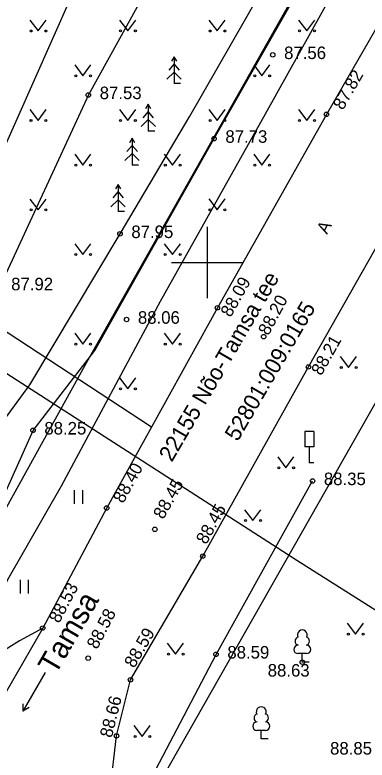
# Model space of a CAD drawing. Extents: x 648748 to 649126, y 6457789 to 6458252.
# Drawn here: x 648789.26 to 648808.93, y 6457972.19 to 6458013.84 of the extents above; entities that cross this region are included whole.
import ezdxf

# ---------------------------------------------------------------- set-up
doc = ezdxf.new("R2010")
doc.units = 0
for name, color, linetype in [('HALJASTUS', 7, 'Continuous'), ('KORGUS-EH2000', 7, 'Continuous'), ('LIIKLUS', 7, 'Continuous'), ('PIIR', 7, 'Continuous'), ('PUU', 7, 'Continuous'), ('SITRASS', 7, 'Continuous'), ('TEE', 7, 'Continuous'), ('VORK', 7, 'Continuous'), ('VTRASS', 7, 'Continuous')]:
    doc.layers.add(name, color=color, linetype=linetype)

msp = doc.modelspace()

# ---------------------------------------------------------------- linework, layer by layer
at = {"layer": 'HALJASTUS'}
for p, q in [((648790.094, 6458013.549), (648790.557, 6458012.942)), ((648790.557, 6458012.942), (648791.003, 6458013.549)), ((648795.092, 6458013.553), (648795.555, 6458012.946)), ((648795.555, 6458012.946), (648796.001, 6458013.553)), ((648800.094, 6458013.549), (648800.557, 6458012.942)), ((648800.557, 6458012.942), (648801.003, 6458013.549)), ((648805.092, 6458013.553), (648805.555, 6458012.946)), ((648805.555, 6458012.946), (648806.001, 6458013.553)), ((648792.594, 6458011.049), (648793.057, 6458010.442)), ((648793.057, 6458010.442), (648793.503, 6458011.049)), ((648802.594, 6458011.049), (648803.057, 6458010.442)), ((648803.057, 6458010.442), (648803.503, 6458011.049)), ((648790.092, 6458008.553), (648790.555, 6458007.946)), ((648790.555, 6458007.946), (648791.001, 6458008.553)), ((648795.092, 6458008.553), (648795.555, 6458007.946)), ((648795.555, 6458007.946), (648796.001, 6458008.553)), ((648800.094, 6458008.549), (648800.557, 6458007.942)), ((648800.557, 6458007.942), (648801.003, 6458008.549)), ((648805.094, 6458008.549), (648805.557, 6458007.942)), ((648805.557, 6458007.942), (648806.003, 6458008.549)), ((648792.594, 6458006.049), (648793.057, 6458005.442)), ((648793.057, 6458005.442), (648793.503, 6458006.049)), ((648797.594, 6458006.049), (648798.057, 6458005.442)), ((648798.057, 6458005.442), (648798.503, 6458006.049)), ((648802.592, 6458006.053), (648803.055, 6458005.446)), ((648803.055, 6458005.446), (648803.501, 6458006.053)), ((648790.094, 6458003.549), (648790.557, 6458002.942)), ((648790.557, 6458002.942), (648791.003, 6458003.549)), ((648800.092, 6458003.552), (648800.555, 6458002.946)), ((648800.555, 6458002.946), (648801.001, 6458003.552)), ((648792.594, 6458001.049), (648793.057, 6458000.442)), ((648793.057, 6458000.442), (648793.503, 6458001.049)), ((648797.592, 6458001.052), (648798.055, 6458000.446)), ((648798.055, 6458000.446), (648798.501, 6458001.052)), ((648784.11, 6457999.185), (648796.889, 6457990.818)), ((648792.594, 6457996.049), (648793.057, 6457995.442)), ((648793.057, 6457995.442), (648793.503, 6457996.049)), ((648797.594, 6457996.049), (648798.057, 6457995.442)), ((648798.057, 6457995.442), (648798.503, 6457996.049)), ((648807.425, 6457994.744), (648807.888, 6457994.137)), ((648807.888, 6457994.137), (648808.334, 6457994.744)), ((648795.092, 6457993.552), (648795.555, 6457992.946)), ((648795.555, 6457992.946), (648796.001, 6457993.552)), ((648803.934, 6457989.13), (648804.397, 6457988.523)), ((648804.397, 6457988.523), (648804.843, 6457989.13)), ((648792.568, 6457987.27), (648792.568, 6457986.509)), ((648793.023, 6457987.27), (648793.023, 6457986.509)), ((648802.078, 6457986.179), (648802.542, 6457985.573)), ((648802.542, 6457985.573), (648802.987, 6457986.179)), ((648789.548, 6457982.264), (648789.548, 6457981.503)), ((648790.003, 6457982.264), (648790.003, 6457981.503)), ((648807.819, 6457979.841), (648808.282, 6457979.234)), ((648808.282, 6457979.234), (648808.728, 6457979.841)), ((648797.764, 6457978.72), (648798.228, 6457978.114)), ((648798.228, 6457978.114), (648798.673, 6457978.72)), ((648795.903, 6457974.121), (648796.366, 6457973.514)), ((648796.366, 6457973.514), (648796.812, 6457974.121))]:
    msp.add_line(p, q, dxfattribs=at)
msp.add_lwpolyline([(648805.429, 6457958.346), (648802, 6457959.786), (648797.402, 6457964.175), (648796.042, 6457966.769), (648795.928, 6457969.389), (648800.489, 6457978.098), (648805.882, 6457987.791)], dxfattribs=at)
for centre in [(648790.156, 6458012.942), (648790.985, 6458012.942), (648795.154, 6458012.946), (648795.983, 6458012.946), (648800.156, 6458012.942), (648800.985, 6458012.942), (648805.154, 6458012.946), (648805.983, 6458012.946), (648792.656, 6458010.442), (648793.485, 6458010.442), (648802.656, 6458010.442), (648803.485, 6458010.442), (648790.154, 6458007.946), (648790.983, 6458007.946), (648795.154, 6458007.946), (648795.983, 6458007.946), (648800.156, 6458007.942), (648800.985, 6458007.942), (648805.156, 6458007.942), (648805.985, 6458007.942), (648792.656, 6458005.442), (648793.485, 6458005.442), (648797.656, 6458005.442), (648798.485, 6458005.442), (648802.654, 6458005.446), (648803.483, 6458005.446), (648790.156, 6458002.942), (648790.985, 6458002.942), (648800.154, 6458002.946), (648800.983, 6458002.946), (648792.656, 6458000.442), (648793.485, 6458000.442), (648797.654, 6458000.446), (648798.483, 6458000.446), (648792.656, 6457995.442), (648793.485, 6457995.442), (648797.656, 6457995.442), (648798.485, 6457995.442), (648807.487, 6457994.137), (648808.316, 6457994.137), (648795.154, 6457992.946), (648795.983, 6457992.946), (648803.996, 6457988.523), (648804.825, 6457988.523), (648802.141, 6457985.573), (648802.97, 6457985.573), (648807.881, 6457979.234), (648808.71, 6457979.234), (648797.827, 6457978.114), (648798.656, 6457978.114), (648795.965, 6457973.514), (648796.794, 6457973.514)]:
    msp.add_circle(centre, 0.055, dxfattribs=at)
at = {"layer": 'KORGUS-EH2000'}
for centre in [(648803.658, 6458011.607), (648793.359, 6458009.366), (648806.656, 6458008.281), (648800.38, 6458006.925), (648795.127, 6458001.6), (648800.566, 6457997.472), (648795.493, 6457996.812), (648803.15, 6457995.858), (648805.652, 6457994.165), (648790.268, 6457990.62), (648805.882, 6457987.791), (648794.382, 6457986.281), (648797.072, 6457985.085), (648799.747, 6457983.584), (648790.808, 6457979.567), (648793.349, 6457977.884), (648800.489, 6457978.098), (648805.307, 6457977.663), (648795.708, 6457976.678), (648794.926, 6457973.54)]:
    msp.add_circle(centre, 0.125, dxfattribs=at)
at = {"layer": 'LIIKLUS'}
for points in [[(648805.45, 6457990.547), (648805.45, 6457989.697)], [(648805.95, 6457990.547), (648805.45, 6457990.547)], [(648805.95, 6457990.547), (648805.95, 6457989.697)], [(648805.95, 6457989.697), (648805.45, 6457989.697)], [(648805.7, 6457989.697), (648805.7, 6457988.797)], [(648805.95, 6457988.797), (648805.7, 6457988.797)]]:
    msp.add_lwpolyline(points, dxfattribs=at)
at = {"layer": 'PIIR'}
for p, q in [((648868.92, 6458128.41), (648793.25, 6457994.41)), ((648796.52, 6457969.47), (648863.67, 6458087.81)), ((648793.25, 6457994.41), (648782.79, 6457975.49))]:
    msp.add_line(p, q, dxfattribs=at)
at = {"layer": 'PUU'}
for p, q in [((648798.146, 6458011.499), (648797.996, 6458011.249)), ((648798.296, 6458011.249), (648798.146, 6458011.499)), ((648798.146, 6458011.499), (648798.146, 6458009.999)), ((648798.146, 6458011.099), (648797.846, 6458010.749)), ((648798.446, 6458010.749), (648798.146, 6458011.099)), ((648798.146, 6458010.649), (648797.746, 6458010.249)), ((648798.546, 6458010.249), (648798.146, 6458010.649)), ((648798.506, 6458009.999), (648798.146, 6458009.999)), ((648796.702, 6458008.845), (648796.552, 6458008.595)), ((648796.852, 6458008.595), (648796.702, 6458008.845)), ((648796.702, 6458008.845), (648796.702, 6458007.345)), ((648796.702, 6458008.445), (648796.402, 6458008.095)), ((648797.002, 6458008.095), (648796.702, 6458008.445)), ((648796.702, 6458007.995), (648796.302, 6458007.595)), ((648797.102, 6458007.595), (648796.702, 6458007.995)), ((648797.062, 6458007.345), (648796.702, 6458007.345)), ((648795.798, 6458006.947), (648795.648, 6458006.697)), ((648795.948, 6458006.697), (648795.798, 6458006.947)), ((648795.798, 6458006.947), (648795.798, 6458005.447)), ((648795.798, 6458006.547), (648795.498, 6458006.197)), ((648796.098, 6458006.197), (648795.798, 6458006.547)), ((648795.798, 6458006.097), (648795.398, 6458005.697)), ((648796.198, 6458005.697), (648795.798, 6458006.097)), ((648796.158, 6458005.447), (648795.798, 6458005.447)), ((648795.02, 6458004.361), (648794.87, 6458004.111)), ((648795.17, 6458004.111), (648795.02, 6458004.361)), ((648795.02, 6458004.361), (648795.02, 6458002.861)), ((648795.02, 6458003.961), (648794.72, 6458003.611)), ((648795.32, 6458003.611), (648795.02, 6458003.961)), ((648795.02, 6458003.511), (648794.62, 6458003.111)), ((648795.42, 6458003.111), (648795.02, 6458003.511)), ((648795.38, 6458002.861), (648795.02, 6458002.861)), ((648805.547, 6457978.138), (648805.067, 6457978.138)), ((648805.307, 6457977.663), (648805.307, 6457978.138)), ((648805.687, 6457977.663), (648805.307, 6457977.663)), ((648803.255, 6457973.844), (648802.775, 6457973.844)), ((648803.015, 6457973.369), (648803.015, 6457973.844)), ((648803.395, 6457973.369), (648803.015, 6457973.369))]:
    msp.add_line(p, q, dxfattribs=at)
for centre, radius, start, end in [((648805.307, 6457979.183), 0.277, 332.58, 207.42), ((648805.137, 6457978.835), 0.233, 109.022, 253.142), ((648805.477, 6457978.835), 0.233, 286.851, 70.986), ((648805.07, 6457978.375), 0.238, 90.002, 269.395), ((648805.545, 6457978.375), 0.238, 270.605, 89.998), ((648803.015, 6457974.889), 0.277, 332.58, 207.42), ((648802.845, 6457974.542), 0.233, 109.022, 253.142), ((648803.185, 6457974.542), 0.233, 286.851, 70.986), ((648802.778, 6457974.082), 0.238, 90.002, 269.395), ((648803.253, 6457974.082), 0.238, 270.605, 89.998)]:
    msp.add_arc(centre, radius, start, end, dxfattribs=at)
at = {"layer": 'SITRASS'}
for points in [[(648838.183, 6458075.605), (648836.351, 6458076.524), (648834.032, 6458074.854), (648828.836, 6458070.077), (648823.373, 6458063.799), (648815.041, 6458050.907), (648808.674, 6458038.587), (648805.571, 6458032.708), (648798.852, 6458019.324), (648793.359, 6458009.366), (648788.414, 6457998.68), (648785.353, 6457991.074), (648783.686, 6457988.513), (648778.988, 6457980.101), (648777.337, 6457977.723), (648774.295, 6457973.649), (648772.508, 6457971.285), (648769.936, 6457967.433)], [(648840.698, 6458076.036), (648840.206, 6458074.518), (648835.992, 6458066.48), (648829.455, 6458054.737), (648823.386, 6458043.337), (648816.202, 6458031.074), (648810.097, 6458020.648), (648803.233, 6458008.294), (648797.369, 6457997.813), (648791.835, 6457987.5), (648788.847, 6457982.267), (648783.409, 6457971.182), (648777.403, 6457959.148), (648772.285, 6457949.688)], [(648771.558, 6457962.366), (648777.323, 6457971.169), (648780.294, 6457977.006), (648783.881, 6457983.462), (648786.386, 6457988.106), (648790.088, 6457993.164), (648795.127, 6458001.6), (648799.018, 6458008.179), (648807.603, 6458023.185), (648816.805, 6458039.666), (648823.715, 6458052.086), (648829.839, 6458063.342), (648833.461, 6458069.995), (648835.841, 6458074.502), (648836.926, 6458074.748), (648838.183, 6458075.605)], [(648772.534, 6457959.145), (648778.305, 6457968.987), (648782.296, 6457976.466), (648786.131, 6457983.091), (648788.533, 6457986.692), (648790.268, 6457990.62), (648793.726, 6457995.075), (648800.38, 6458006.925), (648808.978, 6458022.031), (648818.066, 6458038.429), (648824.931, 6458050.586), (648831.029, 6458061.413), (648834.793, 6458068.888), (648838.183, 6458075.605), (648839.481, 6458073.453), (648841.568, 6458071.264), (648846.872, 6458065.923), (648848.753, 6458063.394)]]:
    msp.add_lwpolyline(points, dxfattribs=at)
at = {"layer": 'TEE'}
for p in [(648790.948, 6457977.084), (648789.702, 6457975.33), (648790.06, 6457975.124)]:
    msp.add_line(p, (648789.702, 6457974.916), dxfattribs=at)
for points in [[(648844.3, 6458074.59), (648841.568, 6458069.96), (648835.932, 6458060.036), (648830.008, 6458049.677), (648824.317, 6458039.384), (648818.356, 6458028.958), (648812.613, 6458018.629), (648806.656, 6458008.281), (648800.566, 6457997.472), (648794.382, 6457986.281), (648790.808, 6457979.567), (648784.572, 6457968.758), (648779.694, 6457960.62), (648774.527, 6457951.036)], [(648795.708, 6457976.678), (648799.747, 6457983.584), (648805.652, 6457994.165), (648811.974, 6458005.315), (648817.667, 6458015.456), (648823.8, 6458025.997), (648829.771, 6458036.425), (648835.506, 6458046.826), (648841.055, 6458057.292), (648846.734, 6458067.377), (648849.159, 6458071.672)], [(648790.808, 6457979.567), (648789.507, 6457978.851), (648786.354, 6457976.876), (648782.643, 6457976.445), (648778.503, 6457977.377), (648774.153, 6457980.236)], [(648805.276, 6457956.318), (648804.322, 6457956.439), (648802.346, 6457956.554), (648796.623, 6457961.769), (648794.959, 6457965.9), (648794.568, 6457970.483), (648794.926, 6457973.54), (648795.708, 6457976.678)]]:
    msp.add_lwpolyline(points, dxfattribs=at)
at = {"layer": 'VORK'}
for p, q in [((648800, 6458002), (648800, 6457998)), ((648798, 6458000), (648802, 6458000))]:
    msp.add_line(p, q, dxfattribs=at)
at = {"layer": 'VTRASS'}
for p, q in [((648818.874, 6458074.609), (648784.329, 6457996.666)), ((648784.329, 6457996.666), (648805.004, 6457983.361)), ((648805.004, 6457983.361), (648828.053, 6457968.736))]:
    msp.add_line(p, q, dxfattribs=at)

# ---------------------------------------------------------------- texts
at = {"layer": 'KORGUS-EH2000'}
for s, p in [(' 87.56', (648804.031, 6458011.373)), (' 87.53', (648793.731, 6458009.133)), (' 87.73', (648800.752, 6458006.692)), (' 87.95', (648795.499, 6458001.367)), (' 87.92', (648788.786, 6457998.447)), (' 88.06', (648795.866, 6457996.579)), (' 88.25', (648790.64, 6457990.387)), (' 88.35', (648806.254, 6457987.557)), (' 88.59', (648800.862, 6457977.865)), ('88.63', (648803.376, 6457976.856)), ('88.85', (648806.859, 6457972.496))]:
    msp.add_text(s, height=0.7, dxfattribs=at).set_placement(p)
for s, rotation, p in [(' 87.82', 60.072, (648807.448, 6458008.254)), (' 88.09', 60.6012, (648801.176, 6457996.671)), (' 88.20', 61.836, (648803.291, 6457995.649)), (' 88.21', 60.4458, (648806.238, 6457993.41)), (' 88.40', 61.0775, (648795.175, 6457986.268)), (' 88.45', 60.1663, (648797.41, 6457985.379)), (' 88.45', 60.8351, (648799.814, 6457983.973)), (' 88.53', 61.9716, (648791.601, 6457979.567)), (' 88.58', 62.6594, (648793.727, 6457978.108)), (' 88.59', 59.6796, (648795.786, 6457977.064)), (' 88.66', 75.9994, (648794.602, 6457973.147))]:
    msp.add_text(s, height=0.7, rotation=rotation, dxfattribs=at).set_placement(p)
at = {"layer": 'PIIR'}
for s, p in [('22155 Nõo-Tamsa tee', (648798.02, 6457988.801)), ('52801:009:0165', (648801.698, 6457989.955))]:
    msp.add_text(s, height=0.9, rotation=59.7525, dxfattribs=at).set_placement(p)
at = {"layer": 'TEE'}
for s, height, rotation, p in [('A', 0.7, 62.2738, (648806.689, 6458001.544)), ('Tamsa', 1.2, 59.8074, (648791.518, 6457976.907))]:
    msp.add_text(s, height=height, rotation=rotation, dxfattribs=at).set_placement(p)

doc.saveas('drawing.dxf')
